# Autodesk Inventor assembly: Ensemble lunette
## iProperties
Shininess: 60.0
Length Units: 11269
Angle Units: 11279
Time Units: 11290
Mass Units: 11283
Length Display Precision: 3
Angle Display Precision: 2
Created: 2000-10
Part Number: Ensemble lunette
Document SubType Name: Assemblage
Density: 0.0
Volumn: 0.0
Area: 0.0
PropertySet Name: Model Information
Control State: 0
Master: False
Checked Out: False
Author: Laurent GAUTHERON
